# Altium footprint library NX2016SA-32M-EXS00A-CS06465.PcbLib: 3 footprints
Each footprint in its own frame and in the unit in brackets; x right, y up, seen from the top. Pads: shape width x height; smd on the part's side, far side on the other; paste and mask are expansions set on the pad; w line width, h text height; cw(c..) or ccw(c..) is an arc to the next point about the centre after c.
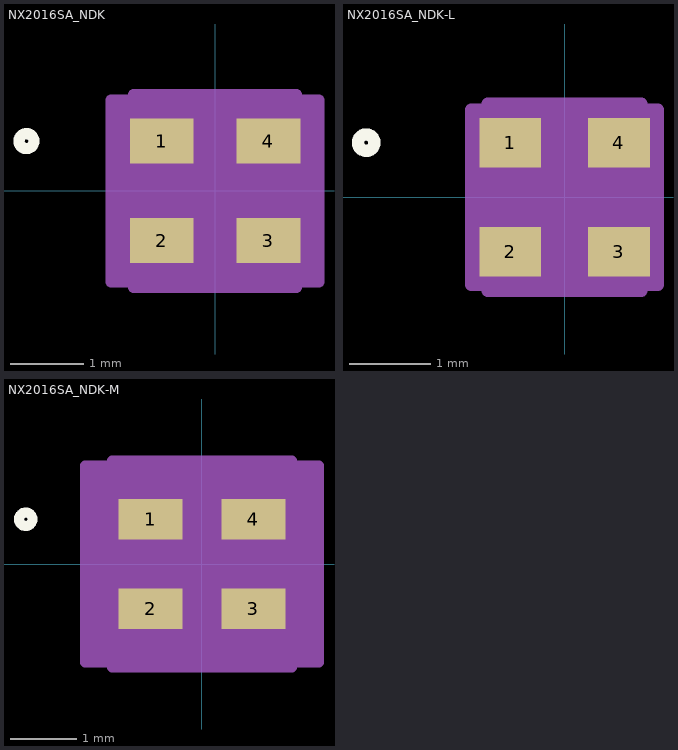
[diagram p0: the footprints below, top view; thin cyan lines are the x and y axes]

## NX2016SA_NDK [mil]
pads (4):
  rect 34x24 smd paste+0 mask+0: 1(-28.5,26.57) 2(-28.5,-26.57) 3(28.5,-26.57) 4(28.5,26.57)
Top Overlay:
  circle w6: c-100.65,26.57 r4
Mechanical 13:
  circle w0: c-11.5,26.57 r3
  lines w0: -12,41.5 ccw(c0,41.5) 12,41.5
  lines w1: -33.5,-41.5 33.5,-41.5 33.5,41.5 -33.5,41.5 -33.5,-41.5
Mechanical 15:
  region: -43.5,-48.57 -55.5,-48.57 -55.5,48.57 -43.5,48.57 -43.5,51.5 43.5,51.5 43.5,48.57 55.5,48.57 55.5,-48.57 43.5,-48.57 43.5,-51.5 -43.5,-51.5
  lines w6: -55.5,-48.57 -55.5,48.57 -43.5,48.57 -43.5,51.5 43.5,51.5 43.5,48.57 55.5,48.57 55.5,-48.57 43.5,-48.57 43.5,-51.5 -43.5,-51.5 -43.5,-48.57 -55.5,-48.57
3D body "NX2016SA_NDK.step": height 20.12, standoff 0, extent -33.5,-41.5 33.5,41.5

## NX2016SA_NDK-L [mil]
pads (4):
  rect 30x24 smd paste+0 mask+0: 1(-26.5,26.57) 2(-26.5,-26.57) 3(26.5,-26.57) 4(26.5,26.57)
Top Overlay:
  circle w6: c-96.65,26.57 r4
Mechanical 13:
  circle w0: c-11.5,26.57 r3
  lines w0: -12,41.5 ccw(c0,41.5) 12,41.5
  lines w1: -33.5,-41.5 33.5,-41.5 33.5,41.5 -33.5,41.5 -33.5,-41.5
Mechanical 15:
  region: -37.5,-42.57 -45.5,-42.57 -45.5,42.57 -37.5,42.57 -37.5,45.5 37.5,45.5 37.5,42.57 45.5,42.57 45.5,-42.57 37.5,-42.57 37.5,-45.5 -37.5,-45.5
  lines w6: -45.5,-42.57 -45.5,42.57 -37.5,42.57 -37.5,45.5 37.5,45.5 37.5,42.57 45.5,42.57 45.5,-42.57 37.5,-42.57 37.5,-45.5 -37.5,-45.5 -37.5,-42.57 -45.5,-42.57
3D body "NX2016SA_NDK.step": height 20.12, standoff 0, extent -33.5,-41.5 33.5,41.5

## NX2016SA_NDK-M [mil]
pads (4):
  rect 38x24 smd paste+0 mask+0: 1(-30.5,26.57) 2(-30.5,-26.57) 3(30.5,-26.57) 4(30.5,26.57)
Top Overlay:
  circle w6: c-104.65,26.57 r4
Mechanical 13:
  circle w0: c-11.5,26.57 r3
  lines w0: -12,41.5 ccw(c0,41.5) 12,41.5
  lines w1: -33.5,-41.5 33.5,-41.5 33.5,41.5 -33.5,41.5 -33.5,-41.5
Mechanical 15:
  region: -53.5,-58.57 -69.5,-58.57 -69.5,58.57 -53.5,58.57 -53.5,61.5 53.5,61.5 53.5,58.57 69.5,58.57 69.5,-58.57 53.5,-58.57 53.5,-61.5 -53.5,-61.5
  lines w6: -69.5,-58.57 -69.5,58.57 -53.5,58.57 -53.5,61.5 53.5,61.5 53.5,58.57 69.5,58.57 69.5,-58.57 53.5,-58.57 53.5,-61.5 -53.5,-61.5 -53.5,-58.57 -69.5,-58.57
3D body "NX2016SA_NDK.step": height 20.12, standoff 0, extent -33.5,-41.5 33.5,41.5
